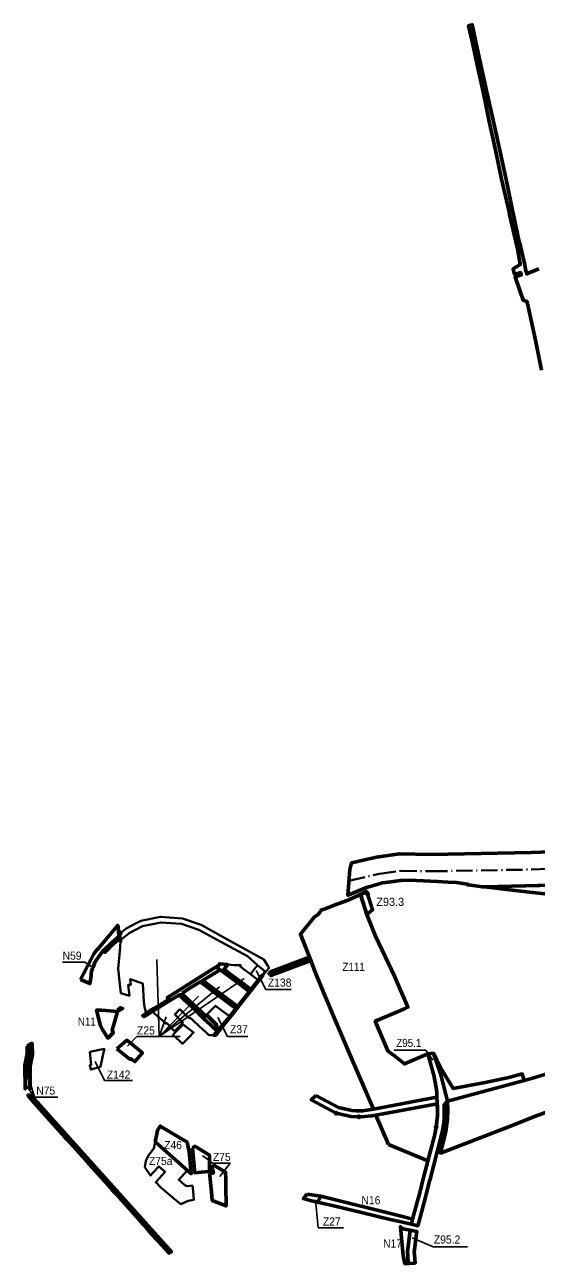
# Model space of a CAD drawing. Extents: x -650277 to -643425, y -1073980 to -1066720.
# Drawn here: x -650277 to -648765, y -1070373 to -1066720 of the extents above; entities that cross this region are included whole.
import ezdxf

# ---------------------------------------------------------------- set-up
doc = ezdxf.new("R2010")
doc.units = 0
doc.header["$LTSCALE"] = 9.6
doc.header["$PDMODE"] = 32
doc.header["$PDSIZE"] = 4.8
doc.linetypes.add('DOT_DASHED', pattern=[7.7, 5, -1.2, 0.3, -1.2])
for name, color, linetype, lineweight in [('1', 7, 'Continuous', 60), ('12', 7, 'Continuous', 40), ('13', 7, 'Continuous', 60), ('15', 7, 'Continuous', 60), ('18', 7, 'Continuous', 60), ('2', 7, 'Continuous', 40), ('24', 7, 'Continuous', 60), ('3', 7, 'Continuous', 60), ('40', 7, 'Continuous', 60), ('42', 7, 'Continuous', 60), ('48', 7, 'Continuous', 60), ('59', 7, 'Continuous', 25), ('60', 7, 'Continuous', 60), ('62', 7, 'DOT_DASHED', 40), ('63', 7, 'Continuous', 25), ('7', 7, 'Continuous', 60), ('9', 7, 'Continuous', 60)]:
    doc.layers.add(name, color=color, linetype=linetype, lineweight=lineweight)

msp = doc.modelspace()

# ---------------------------------------------------------------- linework, layer by layer
at = {"layer": '1'}
for points in [[(-650004.59, -1069747.27), (-649974.86, -1069721.96), (-649966.52, -1069728.87), (-649929.38, -1069759.65), (-649951.56, -1069785.42), (-649963, -1069776.7), (-649965, -1069778.7)], [(-649442.63, -1070176.69), (-649402.29, -1070182.92), (-649404.2, -1070187.43), (-649412.2, -1070200.71), (-649433.3, -1070195.89), (-649453.27, -1070190.02), (-649446.19, -1070180.76)]]:
    msp.add_lwpolyline(points, close=True, dxfattribs=at)
at = {"layer": '12'}
for points in [[(-649639.18, -1069505.96), (-649637.69, -1069506.15), (-649628.36, -1069513.11), (-649609.93, -1069526.87), (-649598.004, -1069510.814), (-649589.257, -1069499.905), (-649619, -1069474), (-649697.525, -1069431.522), (-649762.488, -1069395.854), (-649814.067, -1069377.972), (-649874.391, -1069373.859), (-649929.015, -1069384.784), (-649968.465, -1069405.189), (-649994.293, -1069425.949), (-649994.53, -1069447.61), (-650000.59, -1069511.15), (-649998.81, -1069527.07), (-649998.5, -1069529.88), (-649992.59, -1069582.88), (-649967.81, -1069590.74), (-649971.38, -1069558.79), (-649963.43, -1069557.91), (-649965.26, -1069541.51), (-649928.48, -1069554.57), (-649927.3, -1069572.44)], [(-649927.3, -1069572.44), (-649924.62, -1069608.53), (-649923.17, -1069623.14), (-649918.35, -1069643.45), (-649918.35, -1069643.45), (-649903.292, -1069632.541), (-649877.129, -1069617.006), (-649850.24, -1069600.295), (-649855.34, -1069595.8), (-649805.22, -1069564.32), (-649801.49, -1069561.98), (-649701.57, -1069499.21), (-649701.7, -1069495.89), (-649677.02, -1069498.32), (-649658.01, -1069500.19), (-649647.45, -1069500.23), (-649638.81, -1069500.26), (-649639.18, -1069505.96)], [(-649707.19, -1069577.81), (-649688.76, -1069591.57), (-649670.34, -1069605.34), (-649647.93, -1069622.07), (-649628.8, -1069597.67), (-649613.37, -1069577.98), (-649636.83, -1069560.47), (-649659.26, -1069543.71), (-649681.7, -1069526.96), (-649699.72, -1069513.5), (-649722.6, -1069527.61), (-649749.62, -1069544.29)], [(-649677.02, -1069498.32), (-649687.77, -1069512.44), (-649667.74, -1069527.4), (-649649.31, -1069541.16)], [(-649639.18, -1069505.96), (-649638.81, -1069500.26), (-649647.45, -1069500.23), (-649658.01, -1069500.19), (-649677.02, -1069498.32)], [(-649649.31, -1069541.16), (-649630.88, -1069554.92), (-649608.44, -1069571.69), (-649586.82, -1069544.11), (-649609.93, -1069526.87)], [(-649609.93, -1069526.87), (-649628.36, -1069513.11), (-649637.69, -1069506.15), (-649639.18, -1069505.96)], [(-649597.997, -1069510.805), (-649598.004, -1069510.814), (-649609.93, -1069526.87), (-649586.82, -1069544.11)], [(-649597.935, -1069510.728), (-649597.763, -1069510.865), (-649597.997, -1069510.805)], [(-649571.94, -1069529.24), (-649573.922, -1069527.657), (-649567, -1069519), (-649588, -1069501), (-649589.257, -1069499.905), (-649597.935, -1069510.728)], [(-649586.82, -1069544.11), (-649576.071, -1069530.398), (-649574.1, -1069531.97), (-649571.94, -1069529.24)], [(-649758.29, -1069549.64), (-649785.72, -1069566.56), (-649812.08, -1069582.83)], [(-649671.39, -1069651.93), (-649652.88, -1069628.36), (-649677.124, -1069610.681), (-649696.91, -1069595.47), (-649718.13, -1069579.63), (-649739.75, -1069563.48), (-649758.29, -1069549.64)], [(-649749.62, -1069544.29), (-649748.89, -1069546.2), (-649747.5, -1069547.71), (-649725.62, -1069564.05), (-649707.19, -1069577.81)], [(-649788.91, -1069654.4), (-649781.09, -1069661.69), (-649761.34, -1069680.08), (-649741.61, -1069698.46), (-649732.52, -1069706.92), (-649717.884, -1069707.295), (-649707.985, -1069695.508), (-649723.97, -1069680.13), (-649743.41, -1069661.43), (-649762.85, -1069642.73), (-649782.03, -1069624.28), (-649801.48, -1069605.57), (-649820.02, -1069587.73), (-649846.38, -1069603.8), (-649900.64, -1069636.78)], [(-649812.08, -1069582.83), (-649811.52, -1069584.44), (-649810.49, -1069585.81), (-649793.12, -1069602.51), (-649776.54, -1069618.46), (-649759.97, -1069634.4)], [(-649900.64, -1069636.78), (-649877.82, -1069656.83), (-649859.96, -1069672.53)], [(-649833.94, -1069695.239), (-649819.98, -1069680.92), (-649809.47, -1069670.13), (-649833.38, -1069646.08), (-649818.71, -1069630.64)], [(-649818.71, -1069630.64), (-649802.9, -1069645.96), (-649791, -1069657), (-649788.91, -1069654.4)], [(-649759.97, -1069634.4), (-649743.39, -1069650.35), (-649740.23, -1069647.14)], [(-649740.23, -1069647.14), (-649713.73, -1069620.32), (-649713.73, -1069620.32), (-649693.63, -1069635.33), (-649671.39, -1069651.93)], [(-649859.96, -1069672.53), (-649859.17, -1069673.22), (-649857.49, -1069671.46), (-649833.94, -1069695.239)]]:
    msp.add_lwpolyline(points, dxfattribs=at)
for points in [[(-649713.73, -1069620.32), (-649713.73, -1069620.32), (-649740.23, -1069647.14), (-649709.94, -1069676.28), (-649712.54, -1069678.98), (-649712.89, -1069679.87), (-649712.51, -1069680.75), (-649703.15, -1069689.75), (-649671.39, -1069651.93), (-649693.63, -1069635.33)], [(-649838.99, -1069706.15), (-649820.64, -1069687.33), (-649808.96, -1069675.34), (-649777.94, -1069699.2), (-649792.13, -1069713.65), (-649807.66, -1069729.46), (-649810.41, -1069732.28), (-649819.9, -1069723.61)], [(-649891.21, -1070022.68), (-649895.45, -1070042.15), (-649910.34, -1070061.29), (-649919.55, -1070079.01), (-649922.3, -1070096.9), (-649905.51, -1070122.35), (-649897.03, -1070113.07), (-649880.42, -1070094.87), (-649862.22, -1070111.54), (-649889.87, -1070141.83), (-649874.94, -1070157.19), (-649835.28, -1070191.27), (-649815.33, -1070206.63), (-649794.37, -1070197.2), (-649777.29, -1070193.57), (-649779.75, -1070168.69), (-649781.436, -1070151.591), (-649787.92, -1070152.23), (-649797.33, -1070153.41), (-649804.29, -1070150.68), (-649821.97, -1070134.58), (-649796.4, -1070106.56)]]:
    msp.add_lwpolyline(points, close=True, dxfattribs=at)
at = {"layer": '12', "lineweight": 60}
msp.add_lwpolyline([(-649891.21, -1070022.68), (-649832.007, -1070074.751), (-649784.87, -1070116.76), (-649791.31, -1070051.51), (-649797.45, -1070023.77), (-649876.31, -1069975.93), (-649884.59, -1069988.57)], close=True, dxfattribs=at)
at = {"layer": '13'}
msp.add_line((-649202.375, -1070030.469), (-649085.737, -1070078.201), dxfattribs=at)
for points in [[(-649057.868, -1069910.51), (-649239.635, -1069943.094), (-649202.375, -1070030.469)], [(-649085.737, -1070078.201), (-649066.487, -1070004.267), (-649061.139, -1069979.254), (-649061.138, -1069979.243)]]:
    msp.add_lwpolyline(points, dxfattribs=at)
msp.add_arc((-649347.129, -1069931.193), 290, 350.46253, 4.08974, dxfattribs=at)
msp.add_point((-649061.138, -1069979.243), dxfattribs=at)
at = {"layer": '15'}
msp.add_line((-649057.868, -1069910.51), (-649058.82, -1069890.548), dxfattribs=at)
for points in [[(-648749.97, -1067741.49), (-648767.84, -1067652.98), (-648791.68, -1067543.78), (-648792.97, -1067537.86), (-648804.08, -1067534.88), (-648813.94, -1067506.27), (-648827.86, -1067465.86), (-648809.65, -1067459.77), (-648809.97, -1067458.52), (-648811.21, -1067453.52), (-648811.4, -1067452.79), (-648829.54, -1067458.42), (-648834.01, -1067441.81), (-648812.91, -1067429.16), (-648820.39, -1067386.83), (-648844.16, -1067281.37), (-648845.94, -1067272.85), (-648867.82, -1067176.66), (-648884.26, -1067099.63), (-648899.1, -1067033.34), (-648905.06, -1067006.7), (-648917.76, -1066942.65), (-648924.32, -1066909.55), (-648936.7, -1066852.52), (-648944.75, -1066815.41), (-648955.15, -1066770.11), (-648965.39, -1066723.15), (-648959.88, -1066721.59), (-648954.86, -1066720.16), (-648935.19, -1066812.53), (-648918.27, -1066888.41), (-648914.11, -1066907.05), (-648893.02, -1067002.5), (-648872.31, -1067095.5), (-648851.87, -1067191.04), (-648835.29, -1067268.93), (-648833.66, -1067276.77), (-648816.06, -1067361.71), (-648813.81, -1067365.91), (-648799.58, -1067430.4), (-648796.8, -1067443.1), (-648795.88, -1067447.21), (-648794.7, -1067452.46), (-648793.71, -1067456.88), (-648757.97, -1067441.51)], [(-649710.957, -1069505.107), (-649801.49, -1069561.98), (-649805.22, -1069564.32), (-649855.34, -1069595.8), (-649850.24, -1069600.295), (-649877.129, -1069617.006), (-649903.292, -1069632.541), (-649918.35, -1069643.45), (-649928.67, -1069649.89), (-649924.8, -1069652.19), (-649920.45, -1069649.53), (-649917.38, -1069647.56), (-649900.64, -1069636.78), (-649846.38, -1069603.8), (-649820.02, -1069587.73), (-649801.48, -1069605.57), (-649782.03, -1069624.28), (-649762.85, -1069642.73), (-649743.41, -1069661.43), (-649723.97, -1069680.13), (-649707.985, -1069695.508), (-649717.884, -1069707.295), (-649712.64, -1069707.43), (-649705.28, -1069698.11), (-649700.42, -1069691.8), (-649703.15, -1069689.75), (-649712.51, -1069680.75), (-649712.89, -1069679.87), (-649712.54, -1069678.98), (-649709.94, -1069676.28), (-649740.23, -1069647.14), (-649743.39, -1069650.35), (-649759.97, -1069634.4), (-649776.54, -1069618.46), (-649793.12, -1069602.51), (-649810.49, -1069585.81), (-649811.52, -1069584.44), (-649812.08, -1069582.83)], [(-649812.08, -1069582.83), (-649785.72, -1069566.56), (-649758.29, -1069549.64), (-649749.62, -1069544.29), (-649722.6, -1069527.61)], [(-649722.6, -1069527.61), (-649699.72, -1069513.5), (-649710.957, -1069505.107)], [(-649417.234, -1069885.193), (-649418.94, -1069887.36), (-649430.515, -1069898.514), (-649356.458, -1069937.945)], [(-649246.81, -1069926.27), (-649278.492, -1069930.573), (-649296.851, -1069931.092), (-649310.738, -1069929.342), (-649350.222, -1069920.873), (-649417.234, -1069885.193)], [(-649058.82, -1069890.548), (-649101.89, -1069898.73), (-649246.81, -1069926.27)], [(-649289.95, -1069948.146), (-649282.437, -1069948.342), (-649251.805, -1069945.276), (-649239.635, -1069943.094), (-649057.868, -1069910.51)], [(-649356.458, -1069937.945), (-649312.646, -1069947.342), (-649289.95, -1069948.146)]]:
    msp.add_lwpolyline(points, dxfattribs=at)
at = {"layer": '15', "lineweight": 40}
for points in [[(-649558.601, -1069502.461), (-649570.03, -1069483.83), (-649688.625, -1069418.156), (-649755.971, -1069381.179), (-649810.846, -1069362.154), (-649875.434, -1069357.751), (-649934.363, -1069369.537), (-649945.397, -1069375.277), (-649977.239, -1069391.714), (-649994.329, -1069405.451)], [(-649994.293, -1069425.949), (-649968.465, -1069405.189), (-649929.015, -1069384.784), (-649874.391, -1069373.859)], [(-649874.391, -1069373.859), (-649814.067, -1069377.972), (-649762.488, -1069395.854), (-649697.525, -1069431.522), (-649619, -1069474), (-649589.257, -1069499.905)], [(-649994.329, -1069405.451), (-649994.329, -1069405.451), (-649994.293, -1069425.949), (-649994.293, -1069425.949)], [(-649589.257, -1069499.905), (-649567, -1069519), (-649573.922, -1069527.657), (-649571.94, -1069529.24), (-649561.17, -1069515.83), (-649555.16, -1069508.07), (-649558.601, -1069502.461)]]:
    msp.add_lwpolyline(points, dxfattribs=at)
at = {"layer": '15'}
for points in [[(-650025.31, -1069446.49), (-649998.512, -1069422.926), (-649999.01, -1069415.628), (-650018.873, -1069431.749), (-650043.521, -1069455.69), (-650045.72, -1069459.1), (-650040.012, -1069461.999)], [(-649547.733, -1069530.185), (-649431.761, -1069486.57), (-649435.578, -1069476.772), (-649550.53, -1069519.68), (-649554.83, -1069525), (-649551.32, -1069528.49), (-649549.69, -1069530.14), (-649548.881, -1069530.963)], [(-649677.124, -1069610.681), (-649652.88, -1069628.36), (-649671.39, -1069651.93), (-649703.15, -1069689.75), (-649700.42, -1069691.8), (-649658.13, -1069638.84), (-649651.846, -1069630.82), (-649641.978, -1069618.226), (-649620.45, -1069590.75), (-649574.1, -1069531.97), (-649576.071, -1069530.398), (-649586.82, -1069544.11), (-649608.44, -1069571.69), (-649630.88, -1069554.92), (-649649.31, -1069541.16), (-649667.74, -1069527.4), (-649687.77, -1069512.44), (-649677.02, -1069498.32), (-649701.7, -1069495.89), (-649701.57, -1069499.21), (-649710.957, -1069505.107), (-649699.72, -1069513.5), (-649681.7, -1069526.96), (-649659.26, -1069543.71), (-649636.83, -1069560.47), (-649613.37, -1069577.98), (-649628.8, -1069597.67), (-649647.93, -1069622.07), (-649670.34, -1069605.34), (-649688.76, -1069591.57), (-649707.19, -1069577.81), (-649725.62, -1069564.05), (-649747.5, -1069547.71), (-649748.89, -1069546.2), (-649749.62, -1069544.29), (-649758.29, -1069549.64), (-649739.75, -1069563.48), (-649718.13, -1069579.63), (-649696.91, -1069595.47)], [(-650002.39, -1069633.65), (-650002.65, -1069637.14), (-649987.49, -1069628.6), (-649994.913, -1069626.246)], [(-648800.85, -1069841.52), (-648806.946, -1069821.79), (-648846.924, -1069832.58), (-648916.03, -1069847.12), (-649010.55, -1069865.09), (-649049.22, -1069801.23), (-649069.4, -1069760.67), (-649048, -1069820), (-649032.928, -1069882.782), (-649028.017, -1069902.109)]]:
    msp.add_lwpolyline(points, close=True, dxfattribs=at)
for p in [(-649994.329, -1069405.451), (-649994.293, -1069425.949), (-649356.458, -1069937.945), (-649289.95, -1069948.146)]:
    msp.add_point(p, dxfattribs=at)
at = {"layer": '18'}
for points in [[(-649781.53, -1070041.2), (-649774.45, -1070113.92), (-649754.82, -1070111.89), (-649731.12, -1070109.96), (-649730.96, -1070094.91), (-649730.89, -1070088.96), (-649730.6, -1070061.98), (-649774.73, -1070035.58)], [(-649730.57, -1070115.76), (-649730, -1070122.01), (-649726.22, -1070162.75), (-649725.49, -1070170.64), (-649723.17, -1070195.81), (-649682.04, -1070211.58), (-649683.12, -1070154.14), (-649682.98, -1070132.1), (-649683.57, -1070112.05), (-649717.72, -1070091.61), (-649718.71, -1070093.35), (-649724.36, -1070099.03), (-649719.69, -1070108.94), (-649719.24, -1070114.87)]]:
    msp.add_lwpolyline(points, close=True, dxfattribs=at)
at = {"layer": '2'}
for points in [[(-650053.2, -1069801.11), (-650046.28, -1069767.47), (-650041.591, -1069747.598), (-650084.48, -1069755.86)], [(-650084.48, -1069755.86), (-650082.63, -1069775.78), (-650080.78, -1069795.7), (-650084.63, -1069796.06), (-650081.66, -1069808.87), (-650053.2, -1069801.11)]]:
    msp.add_lwpolyline(points, dxfattribs=at)
at = {"layer": '24'}
for points in [[(-649321.69, -1069307.61), (-649324.3, -1069308.59), (-649359.48, -1069321.82), (-649389.4, -1069333.35), (-649396.52, -1069336.09), (-649403.92, -1069338.26)], [(-649283.702, -1069294.132), (-649284.695, -1069291.033), (-649300.133, -1069297.95), (-649321.69, -1069307.61)], [(-649060.897, -1069861.994), (-649068, -1069825.147), (-649085.41, -1069762.44), (-649085.41, -1069762.44), (-649099.75, -1069768.575), (-649154.76, -1069792.11), (-649184.05, -1069768.45), (-649200.64, -1069756.53), (-649202.99, -1069754.99), (-649241.11, -1069665.9), (-649155.082, -1069629.097), (-649144.57, -1069624.6), (-649184.1, -1069532.2), (-649240.202, -1069414.528), (-649244.08, -1069404.753), (-649265.774, -1069350.068), (-649283.702, -1069294.132)], [(-649403.92, -1069338.26), (-649403.03, -1069340.66), (-649408.81, -1069349.89), (-649422.19, -1069357.99), (-649462.25, -1069408.32), (-649435.578, -1069476.772), (-649431.761, -1069486.57)], [(-649431.761, -1069486.57), (-649416.52, -1069525.68), (-649409.355, -1069544.517), (-649388.438, -1069594.296), (-649379.32, -1069615.71), (-649364.44, -1069650.55), (-649312.03, -1069773.33)], [(-649312.03, -1069773.33), (-649246.81, -1069926.27), (-649101.89, -1069898.73), (-649058.82, -1069890.548)]]:
    msp.add_lwpolyline(points, dxfattribs=at)
msp.add_arc((-649649.71, -1069919.176), 591.583, 2.77379, 5.54687, dxfattribs=at)
at = {"layer": '3'}
msp.add_lwpolyline([(-648722.24, -1069817.54), (-648772.48, -1069832.83), (-648800.85, -1069841.52), (-649028.017, -1069902.109), (-649027.135, -1069928.902), (-649027.953, -1069955.702), (-649032.644, -1069990.371), (-649037.411, -1070011.659), (-649048.918, -1070055.852), (-648931.057, -1070010.171), (-648849.532, -1069978.559), (-648767.83, -1069946.87), (-648562.242, -1069870.301)], dxfattribs=at)
at = {"layer": '40'}
for points in [[(-650002.65, -1069637.14), (-650050.26, -1069633.65), (-650064.77, -1069633.06), (-650052.88, -1069679.49), (-650047.45, -1069690.69), (-650031.64, -1069715.9), (-650015.53, -1069700.21), (-650018.31, -1069690.89), (-650011.15, -1069665.82)], [(-649160.748, -1070243.413), (-649402.29, -1070182.92), (-649404.2, -1070187.43), (-649412.2, -1070200.71), (-649412.2, -1070200.71), (-649408.24, -1070201.62), (-649372.69, -1070209.74), (-649289.83, -1070229.16), (-649229.8, -1070243.94), (-649197.55, -1070251.65), (-649164.91, -1070258.55), (-649160.54, -1070259.96), (-649134.294, -1070266.095), (-649130.712, -1070250.935)]]:
    msp.add_lwpolyline(points, close=True, dxfattribs=at)
at = {"layer": '42'}
msp.add_lwpolyline([(-650112.18, -1069542.11), (-650081.29, -1069484.35), (-650072.5, -1069466.44), (-650063.12, -1069453.54), (-650062.17, -1069454.05), (-650060.29, -1069451.7), (-650057.49, -1069448.18), (-650026.33, -1069411.47), (-650003.73, -1069384.71), (-650002.11, -1069382.8), (-650001.13, -1069388.13), (-649999.95, -1069397.98), (-649999.01, -1069415.628), (-650018.873, -1069431.749), (-650043.521, -1069455.69), (-650045.72, -1069459.1), (-650055.612, -1069471.639), (-650066.897, -1069487.541), (-650069.369, -1069492.132), (-650074.75, -1069506.133), (-650076.365, -1069510.333), (-650079.264, -1069517.874), (-650080.302, -1069525.418), (-650080.802, -1069530.768), (-650082.963, -1069544.736), (-650084.345, -1069554.773)], close=True, dxfattribs=at)
at = {"layer": '48'}
for points in [[(-650270.059, -1069739.232), (-650269.449, -1069762.714), (-650276.214, -1069796.532), (-650275.76, -1069865.474), (-650274.95, -1069865.62), (-650273.87, -1069809.74), (-650273.78, -1069805.2), (-650273.58, -1069794.48), (-650270.15, -1069778.65), (-650267.22, -1069765.1), (-650265.37, -1069741.61), (-650264.91, -1069735.69)], [(-650260.645, -1069868.536), (-650260.748, -1069867.327), (-650261.204, -1069797.969), (-650254.411, -1069764.006), (-650255.21, -1069733.253), (-650255.716, -1069731.162), (-650259.97, -1069732.29), (-650258.74, -1069750.62), (-650257.77, -1069765.2), (-650262.93, -1069794.84), (-650262.77, -1069805.54), (-650262.7, -1069809.89), (-650261.8, -1069868.33)], [(-650257.713, -1069885.547), (-650266.89, -1069883.7), (-650266.68, -1069886.78), (-650262.64, -1069891.57), (-650257.16, -1069898.07), (-650224.71, -1069934.41), (-650209.51, -1069951.43), (-650192.51, -1069970.47), (-650174.3, -1069990.86), (-650157.87, -1070009.26), (-650151.03, -1070016.84), (-650134.26, -1070035.45), (-650106.76, -1070065.96), (-650091.89, -1070082.46), (-650087.18, -1070087.68), (-650076.72, -1070099.29), (-650051.33, -1070127.45), (-650037.78, -1070142.48), (-650018.41, -1070163.97), (-650005.3, -1070178.51), (-649990.95, -1070194.43), (-649977.05, -1070209.85), (-649946.39, -1070243.87), (-649930.46, -1070261.54), (-649924.15, -1070268.55), (-649913.03, -1070282.44), (-649901.59, -1070296.73), (-649871.28, -1070329.01), (-649850.04, -1070351.64), (-649843.513, -1070347.685)]]:
    msp.add_lwpolyline(points, close=True, dxfattribs=at)
at = {"layer": '59'}
for p, q in [((-649410, -1070277), (-649417.769, -1070193.978)), ((-649335, -1070277), (-649410, -1070277))]:
    msp.add_line(p, q, dxfattribs=at)
msp.add_lwpolyline([(-649959, -1069841), (-650041, -1069841), (-650069, -1069785)], dxfattribs=at)
at = {"layer": '60'}
for p, q in [((-649058.858, -1069889.759), (-649057.868, -1069910.51)), ((-649057.134, -1069932.873), (-649057.868, -1069910.51)), ((-649146.163, -1070347.543), (-649145.424, -1070357.637))]:
    msp.add_line(p, q, dxfattribs=at)
for points in [[(-648721.315, -1069164.952), (-648781.015, -1069167.44), (-649076.02, -1069172.683), (-649169.781, -1069171.432), (-649237.512, -1069180.731), (-649277.021, -1069189.913), (-649306.455, -1069196.754), (-649311.633, -1069197.958), (-649316.47, -1069216.91), (-649321.32, -1069281.47), (-649322.09, -1069291.73), (-649322.22, -1069293.54), (-649319.72, -1069292.47), (-649267.5, -1069270.41), (-649242.5, -1069263.3), (-649220.18, -1069257.03), (-649202.63, -1069254.4), (-649165.62, -1069249.43), (-649139.63, -1069248.73), (-649056.95, -1069252.55), (-649026.955, -1069254.366), (-649001.3, -1069255.92), (-648968.49, -1069260.36), (-648968.05, -1069263.06), (-648965.8, -1069262.75), (-648937.91, -1069266.51), (-648924.13, -1069268.21), (-648918.889, -1069268.875), (-648673.267, -1069262.895)], [(-649061.138, -1069979.243), (-649061.138, -1069979.243), (-649061.139, -1069979.254), (-649066.487, -1070004.267), (-649098.65, -1070127.795), (-649110.925, -1070177.113), (-649114.174, -1070189.816), (-649130.712, -1070250.935), (-649134.294, -1070266.095), (-649115.159, -1070270.568), (-649095.152, -1070193.731), (-649093.095, -1070186.132), (-649095.152, -1070193.731), (-649080.924, -1070137.409), (-649080.38, -1070136.996), (-649047.131, -1070009.304), (-649042.468, -1069988.477), (-649042.468, -1069988.477), (-649039.966, -1069973.035), (-649037.98, -1069956.626), (-649037.322, -1069942.129), (-649037.137, -1069928.996), (-649037.665, -1069912.977), (-649028.017, -1069902.109), (-649032.928, -1069882.782), (-649048, -1069820), (-649069.4, -1069760.67), (-649085.41, -1069762.44), (-649068, -1069825.147), (-649060.897, -1069861.994)], [(-649138.43, -1070283.6), (-649146.163, -1070347.543), (-649146.163, -1070347.543)], [(-649125.503, -1070355.837), (-649126.069, -1070348.097), (-649118.257, -1070287.455), (-649138.43, -1070283.6)], [(-649145.424, -1070357.637), (-649143.633, -1070382.123), (-649123.693, -1070380.572), (-649125.503, -1070355.837)]]:
    msp.add_lwpolyline(points, dxfattribs=at)
msp.add_lwpolyline([(-648730.66, -1069290.43), (-648656.242, -1069297.116), (-648673.267, -1069262.895), (-648761.189, -1069265.035), (-648918.889, -1069268.875), (-648909.86, -1069270.02), (-648861.49, -1069275.34), (-648785.92, -1069284.2), (-648730.66, -1069290.43)], close=True, dxfattribs=at)
for centre, radius, start, end in [((-649633.43, -1069918.001), 575.266, 2.81398, 5.58706), ((-649347.129, -1069931.193), 290, 350.46253, 4.08974), ((-649347.129, -1069931.193), 290, 359.66809, 4.08974)]:
    msp.add_arc(centre, radius, start, end, dxfattribs=at)
at = {"layer": '62'}
msp.add_lwpolyline([(-649319.032, -1069251.01), (-649228.433, -1069229.954), (-649166.697, -1069221.478), (-649075.909, -1069222.689), (-648779.53, -1069217.422), (-648667.088, -1069212.737)], dxfattribs=at)
at = {"layer": '63'}
for p, q in [((-649880, -1069711), (-649887, -1069483)), ((-649880, -1069711), (-649629, -1069540)), ((-649880, -1069711), (-649701, -1069564)), ((-649880, -1069711), (-649764, -1069592)), ((-649973, -1069740), (-649946, -1069711)), ((-649880, -1069711), (-649818, -1069711)), ((-650248, -1069890), (-650277, -1069850)), ((-650248, -1069890), (-650261, -1069847))]:
    msp.add_line(p, q, dxfattribs=at)
for points in [[(-650165, -1069491), (-650099, -1069491), (-650081, -1069504)], [(-649490, -1069572), (-649565, -1069572), (-649593, -1069516)], [(-649946, -1069711), (-649880, -1069711), (-649859, -1069653)], [(-649618, -1069711), (-649678, -1069711), (-649706, -1069655)], [(-649185, -1069751), (-649092, -1069751), (-649071, -1069781)], [(-650243, -1069909), (-650248, -1069890), (-650179, -1069890)], [(-649752, -1070063), (-649722, -1070085), (-649670, -1070085), (-649700, -1070125)], [(-648969, -1070333), (-649070, -1070333), (-649132, -1070306)]]:
    msp.add_lwpolyline(points, dxfattribs=at)
at = {"layer": '7'}
msp.add_lwpolyline([(-649138.43, -1070283.6), (-649159.78, -1070279.52), (-649166.86, -1070273.48), (-649162.91, -1070317.47), (-649159.19, -1070358.82), (-649153.64, -1070382.9), (-649148.23, -1070382.48), (-649143.633, -1070382.123), (-649146.163, -1070347.543)], close=True, dxfattribs=at)
at = {"layer": '9'}
msp.add_line((-649283.702, -1069294.132), (-649265.774, -1069350.068), dxfattribs=at)
for points in [[(-649264.156, -1069289.589), (-649266.331, -1069282.804), (-649284.695, -1069291.033), (-649283.702, -1069294.132)], [(-649265.774, -1069350.068), (-649249.069, -1069336.66), (-649264.156, -1069289.589)]]:
    msp.add_lwpolyline(points, dxfattribs=at)
for p in [(-649283.702, -1069294.132), (-649264.156, -1069289.589)]:
    msp.add_point(p, dxfattribs=at)

# ---------------------------------------------------------------- texts
at = {"layer": '59', "width": 0.95}
for s, p in [('Z142', (-650034.387, -1069835.603)), ('Z27', (-649396, -1070270))]:
    msp.add_text(s, height=24, dxfattribs=at).set_placement(p)
at = {"layer": '63'}
msp.add_text('Z93.3', height=24, dxfattribs=at).set_placement((-649238, -1069325))
for s, width, p in [('N59', 0.95, (-650165, -1069484)), ('Z111', 0.9, (-649338, -1069517)), ('Z138', 0.95, (-649558.387, -1069563.603)), ('N11', 0.9, (-650120, -1069679)), ('Z25', 0.95, (-649945, -1069705)), ('Z37', 0.95, (-649670.387, -1069701.603)), ('Z95.1', 0.9, (-649179, -1069742)), ('N75', 0.95, (-650243, -1069883)), ('Z46', 0.95, (-649865, -1070044)), ('Z75a', 0.95, (-649910, -1070091)), ('Z75', 0.95, (-649721, -1070079)), ('N16', 0.95, (-649282, -1070207)), ('N17', 0.95, (-649218, -1070335)), ('Z95.2', 0.95, (-649068, -1070323))]:
    msp.add_text(s, height=24, dxfattribs=dict(at, width=width)).set_placement(p)

doc.saveas('drawing.dxf')
